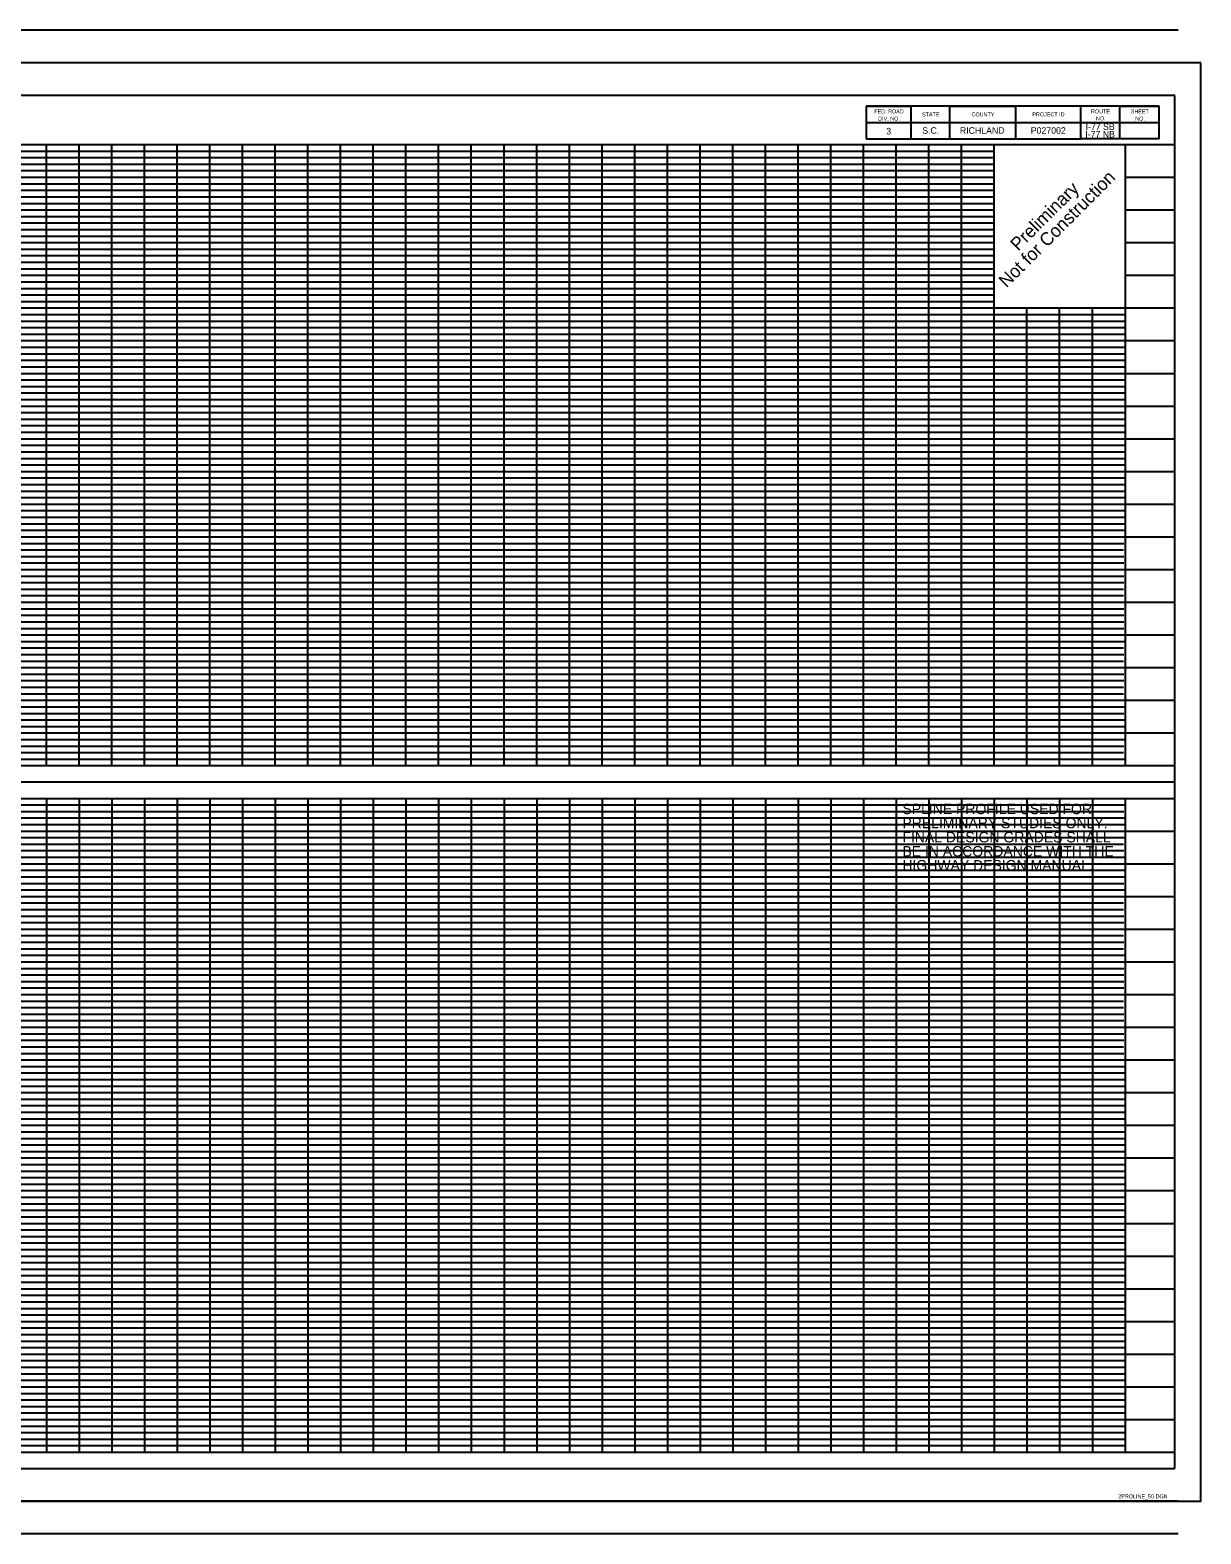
# Model space of a CAD drawing. Extents: x -187 to 1610, y -563 to 587.
# Drawn here: x 714 to 1610, y -563 to 587 of the extents above; entities that cross this region are included whole.
import ezdxf

# ---------------------------------------------------------------- set-up
doc = ezdxf.new("R2010")
doc.units = 0
for name, color, linetype in [('Default', 7, 'Continuous'), ('RD_SHT_Bndy', 7, 'Continuous'), ('RD_SHT_IplotShp', 7, 'Continuous'), ('RD_SHT_MjGrid', 7, 'Continuous'), ('RD_SHT_MnGrid', 7, 'Continuous'), ('RD_SHT_Snap', 7, 'Continuous'), ('RD_SHT_SubGrid', 7, 'Continuous'), ('RD_SHT_TX', 7, 'Continuous')]:
    doc.layers.add(name, color=color, linetype=linetype)

msp = doc.modelspace()

# ---------------------------------------------------------------- linework, layer by layer
at = {"layer": 'RD_SHT_Bndy'}
for p, q in [((1592.6, 587.5), (-167.4, 587.5)), ((1592.6, 562.5), (-167.4, 562.5)), ((1590, 537.5), (-85, 537.5)), ((1354.1, 529.3), (1354.1, 504.3)), ((1354.1, 529.3), (1388.1, 529.3)), ((1518.1, 529.3), (1354.1, 529.3)), ((1388.1, 529.3), (1388.1, 504.3)), ((1418.1, 504.3), (1418.1, 529.3)), ((1418.1, 529.3), (1468.1, 529.3)), ((1468.1, 529.3), (1468.1, 504.3)), ((1518.1, 504.3), (1518.1, 529.3)), ((1578.1, 529.3), (1518.1, 529.3)), ((1548.1, 504.3), (1548.1, 529.3)), ((1548.1, 529.3), (1578.1, 529.3)), ((1578.1, 504.3), (1578.1, 529.3)), ((1590, -512.5), (1590, 537.5)), ((1354.1, 516.8), (1518.1, 516.8)), ((1518.1, 516.8), (1578.1, 516.8)), ((-85.5, 500), (1590, 500)), ((1354.1, 504.3), (1518.1, 504.3)), ((1578.1, 504.3), (1518.1, 504.3)), ((1552, 500), (1552, 25)), ((-85, 25), (1590, 25)), ((-85, 12.5), (1590, 12.5)), ((1552, 0.1), (1552, -500)), ((-85, 0), (1590, 0)), ((1552, 0), (1552, -500)), ((-85, -500), (1590.3, -500)), ((-85, -512.5), (1590, -512.5)), ((1592.6, -537.5), (-167.4, -537.5)), ((1592.6, -562.5), (-167.4, -562.5))]:
    msp.add_line(p, q, dxfattribs=at)
at = {"layer": 'RD_SHT_IplotShp'}
msp.add_lwpolyline([(1610, 562.5), (-186, 562.5), (-186, -537.5), (1610, -537.5)], close=True, dxfattribs=at)
at = {"layer": 'RD_SHT_MjGrid'}
for p, q in [((752, 24.9), (752, 500)), ((802, 24.9), (802, 500)), ((852, 25), (852, 500)), ((902, 25), (902, 500)), ((952, 25), (952, 500)), ((1002, 25), (1002, 500)), ((1052, 24.8), (1052, 500)), ((1102, 24.9), (1102, 500)), ((1152, 24.9), (1152, 500)), ((1202, 25), (1202, 500)), ((1252, 25), (1252, 500)), ((1302, 24.9), (1302, 500)), ((1352, 25), (1352, 500)), ((1402, 25), (1402, 500)), ((1452, 25), (1452, 500)), ((-85, 475), (1452, 475)), ((1552, 475), (1590, 475)), ((1552, 450), (1590, 450)), ((-85, 425), (1452, 425)), ((1552, 425), (1590, 425)), ((1552, 400), (1590, 400)), ((-85, 375), (1590, 375)), ((1502, 25), (1502, 375)), ((-85, 325), (1590, 325)), ((-85, 275), (1590, 275)), ((-85, 225), (1590, 225)), ((-85, 175), (1590, 175)), ((-85, 125), (1590, 125)), ((-85, 75), (1590, 75)), ((752, 0), (752, -500)), ((802, 0), (802, -500)), ((852, 0), (852, -500)), ((902, 0), (902, -500)), ((952, 0), (952, -500)), ((1002, 0), (1002, -500)), ((1052, 0), (1052, -500)), ((1102, 0), (1102, -500)), ((1152, 0), (1152, -500)), ((1202, 0), (1202, -500)), ((1252, 0), (1252, -500)), ((1302, 0), (1302, -500)), ((1352, 0), (1352, -500)), ((1402, 0), (1402, -500)), ((1452, 0), (1452, -500)), ((1502, 0), (1502, -500)), ((-85, -50), (1590, -50)), ((-85, -100), (1590, -100)), ((-85, -150), (1590, -150)), ((-85, -200), (1590, -200)), ((-85, -250), (1590, -250)), ((-85, -300), (1590, -300)), ((-85, -350), (1590, -350)), ((-85, -400), (1590, -400)), ((-85, -450), (1590, -450))]:
    msp.add_line(p, q, dxfattribs=at)
at = {"layer": 'RD_SHT_MnGrid'}
for p, q in [((727, 24.9), (727, 500)), ((777, 24.9), (777, 500)), ((827, 25), (827, 500)), ((877, 24.9), (877, 500)), ((927, 25), (927, 500)), ((977, 24.9), (977, 500)), ((1027, 24.9), (1027, 500)), ((1077, 24.9), (1077, 500)), ((1127, 25), (1127, 500)), ((1177, 25.1), (1177, 500)), ((1227, 24.9), (1227, 500)), ((1277, 25), (1277, 500)), ((1327, 24.9), (1327, 500)), ((1377, 24.9), (1377, 500)), ((1427, 24.9), (1427, 500)), ((-85, 450), (1452, 450)), ((-85, 400), (1452, 400)), ((1477, 24.9), (1477, 375)), ((1527, 25), (1527, 375)), ((-85, 350), (1590, 350)), ((-85, 300), (1590, 300)), ((-85, 250), (1590, 250)), ((-85, 200), (1590, 200)), ((-85, 150), (1590, 150)), ((-85, 100), (1590, 100)), ((-85, 50), (1590, 50)), ((727, 0), (727, -500)), ((777, 0), (777, -500)), ((827, 0), (827, -500)), ((877, 0), (877, -500)), ((927, 0), (927, -500)), ((977, 0), (977, -500)), ((1027, 0), (1027, -500)), ((1077, 0), (1077, -500)), ((1127, 0), (1127, -500)), ((1177, 0), (1177, -500)), ((1227, 0), (1227, -500)), ((1277, 0), (1277, -500)), ((1327, 0), (1327, -500)), ((1377, 0), (1377, -500)), ((1427, 0), (1427, -500)), ((1477, 0), (1477, -500)), ((1527, 0), (1527, -500)), ((-85, -25), (1590, -25)), ((-85, -75), (1590, -75)), ((-85, -125), (1590, -125)), ((-85, -175), (1590, -175)), ((-85, -225), (1590, -225)), ((-85, -275), (1590, -275)), ((-85, -325), (1590, -325)), ((-85, -375), (1590, -375)), ((-85, -425), (1590, -425)), ((-85, -475), (1590, -475))]:
    msp.add_line(p, q, dxfattribs=at)
at = {"layer": 'RD_SHT_Snap'}
msp.add_line((1610, -537.5), (1610, 562.5), dxfattribs=at)
at = {"layer": 'RD_SHT_SubGrid'}
for p, q in [((-47.9, 495), (1452, 495)), ((-47.9, 490), (1452, 490)), ((-47.9, 485), (1452, 485)), ((-47.9, 480), (1452, 480)), ((-48, 470), (1452, 470)), ((-48, 465), (1452, 465)), ((-48, 460), (1452, 460)), ((-47.9, 455), (1452, 455)), ((-48, 445), (1452, 445)), ((-48, 440), (1452, 440)), ((-48, 435), (1452, 435)), ((-47.9, 430), (1452, 430)), ((-48, 420), (1452, 420)), ((-48, 415), (1452, 415)), ((-48, 410), (1452, 410)), ((-48, 405), (1452, 405)), ((-47.9, 395), (1452, 395)), ((-48, 390), (1452, 390)), ((-48, 385), (1452, 385)), ((-48, 380), (1452, 380)), ((-47.9, 370), (1551.9, 370)), ((-48, 365), (1551.9, 365)), ((-48, 360), (1551.9, 360)), ((-47.9, 355), (1551.8, 355)), ((-48, 335), (1551.8, 335)), ((-47.9, 345), (1551.6, 345)), ((-47.9, 340), (1551.6, 340)), ((-48, 330), (1551.8, 330)), ((-47.9, 330), (1551.8, 330)), ((-48, 320), (1551.8, 320)), ((-48, 315), (1551.8, 315)), ((-48, 310), (1551.8, 310)), ((-48, 305), (1551.8, 305)), ((-48, 295), (1551.8, 295)), ((-48, 290), (1551.8, 290)), ((-48, 285), (1551.8, 285)), ((-48, 280), (1551.8, 280)), ((-48, 270), (1551.8, 270)), ((-48, 265), (1551.8, 265)), ((-48, 260), (1551.8, 260)), ((-48, 255), (1551.8, 255)), ((-48, 245), (1551.8, 245)), ((-48, 240), (1551.8, 240)), ((-48, 235), (1551.8, 235)), ((-48, 230), (1551.8, 230)), ((-48, 220), (1551.8, 220)), ((-48, 215), (1551.8, 215)), ((-48, 210), (1551.8, 210)), ((-48, 205), (1551.8, 205)), ((-48, 195), (1551.2, 195)), ((-48, 195), (1550.7, 195)), ((-48, 190), (1550.7, 190)), ((-48, 185), (1551.2, 185)), ((-48, 180), (1551.2, 180)), ((-47.9, 170), (1551.2, 170)), ((-47.9, 165), (1551.2, 165)), ((-47.9, 160), (1550.7, 160)), ((-47.9, 155), (1550.7, 155)), ((-48, 145), (1551.2, 145)), ((-48, 140), (1551.2, 140)), ((-48, 135), (1551.2, 135)), ((-48, 130), (1551.2, 130)), ((-47.9, 120), (1551.8, 120)), ((-48, 115), (1550.7, 115)), ((-48, 110), (1551.2, 110)), ((-48, 105), (1550.7, 105)), ((-48, 95), (1551.2, 95)), ((-48, 90), (1551.2, 90)), ((-48, 85), (1550.7, 85)), ((-48, 80), (1550.7, 80)), ((-48, 70), (1551.8, 70)), ((-48, 65), (1551.2, 65)), ((-48, 60), (1551.8, 60)), ((-48, 55), (1551.8, 55)), ((-48, 45), (1551.8, 45)), ((-48, 40), (1551.2, 40)), ((-48, 35), (1550.7, 35)), ((-48, 30), (1551.8, 30)), ((-48, -5), (1551.8, -5)), ((-48, -10), (1551.2, -10)), ((-48, -15), (1551.8, -15)), ((-47.9, -20), (1551.8, -20)), ((-48, -30), (1551.8, -30)), ((-48, -35), (1550.7, -35)), ((-48, -40), (1551.2, -40)), ((-48, -45), (1551.8, -45)), ((-48, -55), (1551.8, -55)), ((-48, -60), (1551.8, -60)), ((-48, -65), (1551.2, -65)), ((-48, -70), (1551.8, -70)), ((-48, -80), (1550.7, -80)), ((-48, -85), (1550.7, -85)), ((-48, -90), (1551.2, -90)), ((-48, -95), (1551.2, -95)), ((-48, -105), (1550.7, -105)), ((-48, -110), (1551.2, -110)), ((-48, -115), (1550.7, -115)), ((-47.9, -120), (1551.8, -120)), ((-48, -130), (1551.2, -130)), ((-48, -135), (1551.2, -135)), ((-48, -140), (1551.2, -140)), ((-48, -145), (1551.2, -145)), ((-47.9, -155), (1550.7, -155)), ((-47.9, -160), (1550.7, -160)), ((-47.9, -165), (1551.2, -165)), ((-47.9, -170), (1551.2, -170)), ((-48, -180), (1551.2, -180)), ((-48, -185), (1551.2, -185)), ((-48, -190), (1550.7, -190)), ((-48, -195), (1551.2, -195)), ((-48, -195), (1550.7, -195)), ((-48, -205), (1551.8, -205)), ((-48, -210), (1551.8, -210)), ((-48, -215), (1551.8, -215)), ((-48, -220), (1551.8, -220)), ((-48, -230), (1551.8, -230)), ((-48, -235), (1551.8, -235)), ((-48, -240), (1551.8, -240)), ((-48, -245), (1551.8, -245)), ((-48, -255), (1551.8, -255)), ((-48, -260), (1551.8, -260)), ((-48, -265), (1551.8, -265)), ((-48, -270), (1551.8, -270)), ((-48, -280), (1551.8, -280)), ((-48, -285), (1551.8, -285)), ((-48, -290), (1551.8, -290)), ((-48, -295), (1551.8, -295)), ((-48, -305), (1551.8, -305)), ((-48, -310), (1551.8, -310)), ((-48, -315), (1551.8, -315)), ((-48, -320), (1551.8, -320)), ((-48, -330), (1551.8, -330)), ((-47.9, -330), (1551.8, -330)), ((-48, -335), (1551.8, -335)), ((-47.9, -340), (1551.6, -340)), ((-47.9, -345), (1551.6, -345)), ((-47.9, -355), (1551.8, -355)), ((-48, -360), (1551.9, -360)), ((-48, -365), (1551.9, -365)), ((-47.9, -370), (1551.9, -370)), ((-48, -380), (1551.9, -380)), ((-48, -385), (1551.9, -385)), ((-48, -390), (1551.9, -390)), ((-47.9, -395), (1551.9, -395)), ((-48, -405), (1551.9, -405)), ((-48, -410), (1551.9, -410)), ((-48, -415), (1551.9, -415)), ((-48, -420), (1551.8, -420)), ((-48, -435), (1551.8, -435)), ((-47.9, -430), (1551.6, -430)), ((-48, -440), (1551.8, -440)), ((-48, -445), (1551.8, -445)), ((-47.9, -455), (1551.8, -455)), ((-48, -460), (1551.8, -460)), ((-48, -465), (1551.8, -465)), ((-48, -470), (1551.8, -470)), ((-47.9, -480), (1551.8, -480)), ((-47.9, -485), (1551.8, -485)), ((-47.9, -490), (1551.8, -490)), ((-47.9, -495), (1551.8, -495))]:
    msp.add_line(p, q, dxfattribs=at)

# ---------------------------------------------------------------- texts
at = {"layer": 'Default'}
for s, p in [('Not for Construction', (1461.3, 389.9)), ('Preliminary', (1470.3, 418))]:
    msp.add_text(s, height=10, rotation=45, dxfattribs=at).set_placement(p)
for s, p in [('SPLINE PROFILE USED FOR', (1381.7, -12.1)), ('PRELIMINARY STUDIES ONLY.', (1381.7, -22.9)), ('FINAL DESIGN GRADES SHALL', (1381.7, -33.7)), ('BE IN ACCORDANCE WITH THE', (1381.7, -44.5)), ('HIGHWAY DESIGN MANUAL.', (1381.7, -55.2))]:
    msp.add_text(s, height=8, dxfattribs=at).set_placement(p)
at = {"layer": 'RD_SHT_TX'}
for s, height, p in [('FED. ROAD', 3, (1360.2, 523.8)), ('DIV. NO.', 3, (1363.2, 518.3)), ('STATE', 3, (1396.7, 521.5)), ('COUNTY', 3, (1434.6, 521.5)), ('PROJECT ID', 3, (1481.1, 521.5)), ('ROUTE', 3, (1526, 523.8)), ('NO.', 3, (1529.8, 518.4)), ('SHEET', 3, (1556.4, 523.8)), ('NO.', 3, (1559.8, 518.3)), ('3', 5, (1369.4, 507.7)), ('S.C.', 5, (1396.9, 508.2)), ('RICHLAND', 5, (1425.7, 508.2)), ('P027002', 5, (1479.9, 508.2)), ('I-77 NB', 5, (1521.6, 505.3)), ('I-77 SB', 5, (1521.8, 511.1)), ('2PROLINE_50.DGN', 3, (1546.8, -535.3))]:
    msp.add_text(s, height=height, dxfattribs=at).set_placement(p)

doc.saveas('drawing.dxf')
